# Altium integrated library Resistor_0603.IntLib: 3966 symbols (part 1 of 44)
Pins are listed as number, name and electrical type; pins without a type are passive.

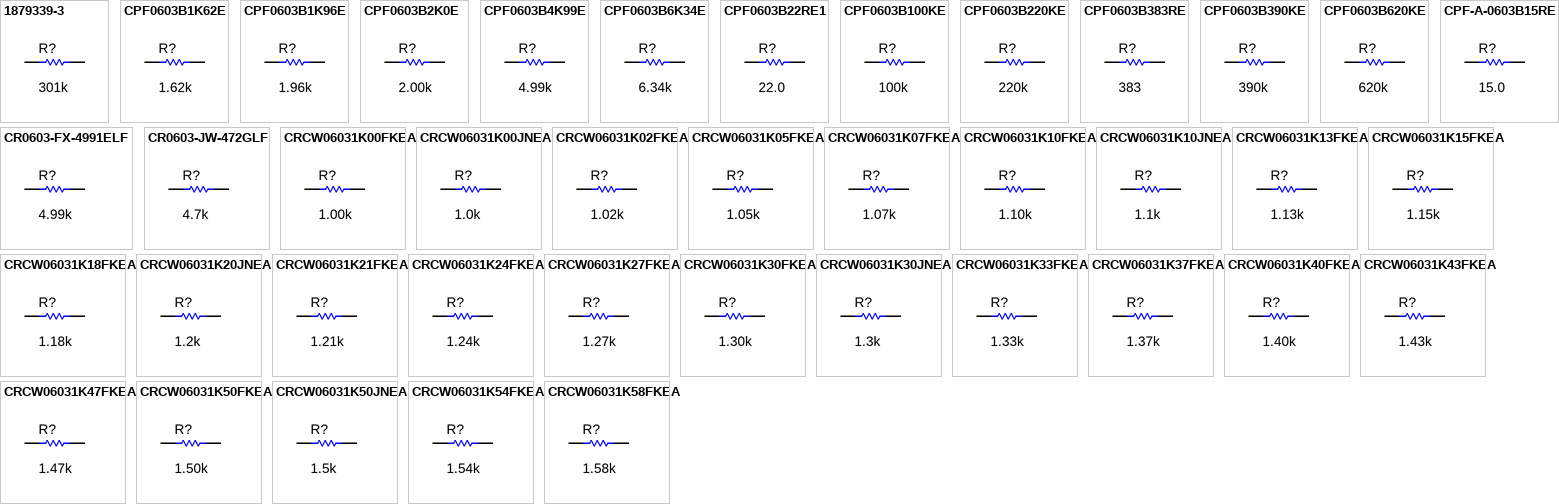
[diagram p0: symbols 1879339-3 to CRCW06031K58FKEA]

## 1879339-3
designator R?  ValueDisplayed: 301k  (hidden comment: 1879339-3)
RES, 301 k, 1%, 0.063 W, 0603; Manufacturer: TE Connectivity; CompType: Resistor; Value: 301k; Res_ohm: 301000; Tolerance_%: 1; Power_W: 0.063; Value2: 0.063W; VDC_V: 50; TempCo: 50 ppm/C; SizeArea_mm2: 1.28; SizeX_mm: 1.6; SizeY_mm: 0.8; EIA_Code: E96; U/M: EA; AEC Category: Q200; Green_Lifecycle: Active; Green_REACh: Passed
signal-integrity model Resistor
simulation model Resistor
footprint 0603
footprint 0603M
footprint 0603L
footprint 0603_HV
footprint 0603S
pins: 1, 2

## CPF0603B1K62E
designator R?  ValueDisplayed: 1.62k  (hidden comment: CPF0603B1K62E)
RES, 1.62 k, 0.1%, 0.063 W, 0603; Manufacturer: TE Connectivity; CompType: Resistor; Value: 1.62k; Res_ohm: 1620; Value_Code: 1k62; Tolerance_%: 0.1; Power_W: 0.063; Value2: 0.063W; VDC_V: 50; TempCo: 25 ppm/C; SizeArea_mm2: 1.28; SizeX_mm: 1.6; SizeY_mm: 0.8; SizeZ_mm: 1; EIA_Code: E192; U/M: EA; AEC Category: Q200
signal-integrity model Resistor
simulation model Resistor
footprint 0603
footprint 0603M
footprint 0603L
footprint 0603_HV
footprint 0603S
pins: 1, 2

## CPF0603B1K96E
designator R?  ValueDisplayed: 1.96k  (hidden comment: CPF0603B1K96E)
RES, 1.96 k, 0.1%, 0.063 W, 0603; Manufacturer: TE Connectivity; CompType: Resistor; Value: 1.96k; Res_ohm: 1960; Value_Code: 1k96; Tolerance_%: 0.1; Power_W: 0.063; Value2: 0.063W; VDC_V: 50; TempCo: 25 ppm/C; SizeArea_mm2: 1.28; SizeX_mm: 1.6; SizeY_mm: 0.8; SizeZ_mm: 1; EIA_Code: E192; U/M: EA; AEC Category: Q200
signal-integrity model Resistor
simulation model Resistor
footprint 0603
footprint 0603M
footprint 0603L
footprint 0603_HV
footprint 0603S
pins: 1, 2

## CPF0603B2K0E
designator R?  ValueDisplayed: 2.00k  (hidden comment: CPF0603B2K0E)
RES, 2.00 k, 0.1%, 0.063 W, 0603; Manufacturer: TE Connectivity; CompType: Resistor; Value: 2.00k; Res_ohm: 2000; Value_Code: 2k00; Tolerance_%: 0.1; Power_W: 0.063; Value2: 0.063W; VDC_V: 50; TempCo: 25 ppm/C; SizeArea_mm2: 1.24; SizeX_mm: 1.55; SizeY_mm: 0.8; SizeZ_mm: 0.55; EIA_Code: E192; U/M: EA; AEC Category: Q200; AEC Qualified: N; Green_Lifecycle: Active; Green_REACh: Passed
signal-integrity model Resistor
simulation model Resistor
footprint CPF0603
pins: 1, 2

## CPF0603B4K99E
designator R?  ValueDisplayed: 4.99k  (hidden comment: CPF0603B4K99E)
RES, 4.99 k, 0.1%, 0.063 W, 0603; Manufacturer: TE Connectivity; CompType: Resistor; Value: 4.99k; Res_ohm: 4990; Value_Code: 4k99; Tolerance_%: 0.1; Power_W: 0.063; Value2: 0.063W; VDC_V: 50; TempCo: 25 ppm/C; SizeArea_mm2: 1.28; SizeX_mm: 1.6; SizeY_mm: 0.8; SizeZ_mm: 1; EIA_Code: E192; U/M: EA; AEC Category: Q200; Green_Lifecycle: Active; Green_REACh: Passed
signal-integrity model Resistor
simulation model Resistor
footprint 0603
footprint 0603M
footprint 0603L
footprint 0603_HV
footprint 0603S
pins: 1, 2

## CPF0603B6K34E
designator R?  ValueDisplayed: 6.34k  (hidden comment: CPF0603B6K34E)
RES, 6.34 k, 0.1%, 0.063 W, 0603; Manufacturer: TE Connectivity; CompType: Resistor; Value: 6.34k; Res_ohm: 6340; Value_Code: 6k34; Tolerance_%: 0.1; Power_W: 0.063; Value2: 0.063W; VDC_V: 50; TempCo: 25 ppm/C; SizeArea_mm2: 1.28; SizeX_mm: 1.6; SizeY_mm: 0.8; SizeZ_mm: 1; EIA_Code: E192; U/M: EA; AEC Category: Q200
signal-integrity model Resistor
simulation model Resistor
footprint 0603
footprint 0603M
footprint 0603L
footprint 0603_HV
footprint 0603S
pins: 1, 2

## CPF0603B22RE1
designator R?  ValueDisplayed: 22.0  (hidden comment: CPF0603B22RE1)
RES, 22.0, 0.1%, 0.063 W, 0603; Manufacturer: TE Connectivity; CompType: Resistor; Value: 22; Value_Code: 22R0; Tolerance_%: 0.1; Power_W: 0.063; Value2: 0.063W; TempCo: 25 ppm/C; SizeArea_mm2: 1.24; SizeX_mm: 1.55; SizeY_mm: 0.8; SizeZ_mm: 0.55; U/M: EA; AEC Category: Q200; AEC Qualified: N
signal-integrity model Resistor
simulation model Resistor
footprint CPF0603
pins: 1, 2

## CPF0603B100KE
designator R?  ValueDisplayed: 100k  (hidden comment: CPF0603B100KE)
RES, 100 k, 0.1%, 0.063 W, 0603; Manufacturer: TE Connectivity; CompType: Resistor; Value: 100k; Res_ohm: 100000; Tolerance_%: 0.1; Power_W: 0.063; Value2: 0.063W; VDC_V: 50; TempCo: 25 ppm/C; SizeArea_mm2: 1.28; SizeX_mm: 1.6; SizeY_mm: 0.8; SizeZ_mm: 1; EIA_Code: E192; U/M: EA; AEC Category: Q200; Green_Lifecycle: Active; Green_REACh: Passed
signal-integrity model Resistor
simulation model Resistor
footprint 0603
footprint 0603M
footprint 0603L
footprint 0603_HV
footprint 0603S
pins: 1, 2

## CPF0603B220KE
designator R?  ValueDisplayed: 220k  (hidden comment: CPF0603B220KE)
RES, 220 k, 0.1%, 0.063 W, 0603; Manufacturer: TE Connectivity; CompType: Resistor; Value: 220k; Res_ohm: 220000; Tolerance_%: 0.1; Power_W: 0.063; Value2: 0.063W; VDC_V: 50; TempCo: 25 ppm/C; SizeArea_mm2: 1.28; SizeX_mm: 1.6; SizeY_mm: 0.8; SizeZ_mm: 1; U/M: EA; AEC Category: Q200; AEC Qualified: N
signal-integrity model Resistor
simulation model Resistor
footprint 0603
footprint 0603M
footprint 0603L
footprint 0603_HV
footprint 0603S
pins: 1, 2

## CPF0603B383RE
designator R?  ValueDisplayed: 383  (hidden comment: CPF0603B383RE)
RES, 383, 0.1%, 0.063 W, 0603; Manufacturer: TE Connectivity; CompType: Resistor; Value: 383; Value_Code: 383R; Tolerance_%: 0.1; Power_W: 0.063; Value2: 0.063W; VDC_V: 50; TempCo: 25 ppm/C; SizeArea_mm2: 1.28; SizeX_mm: 1.6; SizeY_mm: 0.8; SizeZ_mm: 1; EIA_Code: E192; U/M: EA; AEC Category: Q200; Green_Lifecycle: Active; Green_REACh: Passed
signal-integrity model Resistor
simulation model Resistor
footprint 0603
footprint 0603M
footprint 0603L
footprint 0603_HV
footprint 0603S
pins: 1, 2

## CPF0603B390KE
designator R?  ValueDisplayed: 390k  (hidden comment: CPF0603B390KE)
RES, 390 k, 0.1%, 0.1 W, 0603; Manufacturer: TE Connectivity; CompType: Resistor; Value: 390k; Res_ohm: 390000; Tolerance_%: 0.1; Value2: 0.1W; VDC_V: 50; TempCo: 25 ppm/C; SizeArea_mm2: 1.28; SizeX_mm: 1.6; SizeY_mm: 0.8; SizeZ_mm: 1; U/M: EA; AEC Category: Q200; AEC Qualified: N; Green_Lifecycle: Active; Green_REACh: Passed
signal-integrity model Resistor
simulation model Resistor
footprint 0603
footprint 0603M
footprint 0603L
footprint 0603_HV
footprint 0603S
pins: 1, 2

## CPF0603B620KE
designator R?  ValueDisplayed: 620k  (hidden comment: CPF0603B620KE)
RES, 620 k, 0.1%, 0.063 W, 0603; Manufacturer: TE Connectivity; CompType: Resistor; Value: 620k; Res_ohm: 620000; Tolerance_%: 0.1; Power_W: 0.063; Value2: 0.063W; VDC_V: 50; TempCo: 25 ppm/C; SizeArea_mm2: 1.24; SizeX_mm: 1.55; SizeY_mm: 0.8; SizeZ_mm: 0.55; U/M: EA; AEC Category: Q200; AEC Qualified: N
signal-integrity model Resistor
simulation model Resistor
footprint CPF0603
pins: 1, 2

## CPF-A-0603B15RE
designator R?  ValueDisplayed: 15.0  (hidden comment: CPF-A-0603B15RE)
RES, 15.0, 0.1%, 0.063 W, AEC-Q200 Grade 0, 0603; Manufacturer: TE Connectivity; CompType: Resistor; Value: 15.0; Res_ohm: 15; Value_Code: 15R0; Tolerance_%: 0.1; Power_W: 0.063; Value2: 0.063W; TempCo: 25 ppm/C; SizeArea_mm2: 1.24; SizeX_mm: 1.55; SizeY_mm: 0.8; SizeZ_mm: 0.55; EIA_Code: E192; U/M: EA; AEC Category: Q200; AEC Qualified: Y; AEC Grade: 0
signal-integrity model Resistor
simulation model Resistor
footprint CPF0603
pins: 1, 2

## CR0603-FX-4991ELF
designator R?  ValueDisplayed: 4.99k  (hidden comment: CR0603-FX-4991ELF)
RES, 4.99 k, 1%, 0.1 W, 0603; Manufacturer: Bourns; CompType: Resistor; Value: 4.99k; Res_ohm: 4990; Value_Code: 4k99; Tolerance_%: 1; Power_W: 0.1; Value2: 0.1W; TempCo: 100 ppm/C; SizeArea_mm2: 1.28; SizeX_mm: 1.6; SizeY_mm: 0.8; EIA_Code: E96; U/M: EA; AEC Category: Q200; Green_Lifecycle: Active; Green_REACh: Passed
signal-integrity model Resistor
simulation model Resistor
footprint 0603
footprint 0603M
footprint 0603L
footprint 0603_HV
footprint 0603S
pins: 1, 2

## CR0603-JW-472GLF
designator R?  ValueDisplayed: 4.7k  (hidden comment: CR0603-JW-472GLF)
RES, 4.7 k, 5%, 0.1 W, 0603; Manufacturer: Bourns; CompType: Resistor; Value: 4.7k; Res_ohm: 4700; Value_Code: 4k70; Tolerance_%: 5; Power_W: 0.1; Value2: 0.1W; VDC_V: 50; TempCo: 200 ppm/C; SizeArea_mm2: 1.28; SizeX_mm: 1.6; SizeY_mm: 0.8; SizeZ_mm: 1; EIA_Code: E24; U/M: EA; AEC Category: Q200; AEC Qualified: N; Green_Lifecycle: Active; Green_REACh: Passed
signal-integrity model Resistor
simulation model Resistor
footprint 0603
footprint 0603M
footprint 0603L
footprint 0603_HV
footprint 0603S
pins: 1, 2

## CRCW06031K00FKEA
designator R?  ValueDisplayed: 1.00k  (hidden comment: CRCW06031K00FKEA)
RES, 1.00 k, 1%, 0.1 W, 0603; Manufacturer: Vishay-Dale; CompType: Resistor; Value: 1.00k; Res_ohm: 1000; Value_Code: 1k00; Tolerance_%: 1; Power_W: 0.1; Value2: 0.1W; VDC_V: 75; TempCo: 100 ppm/C; SizeArea_mm2: 1.28; SizeX_mm: 1.6; SizeY_mm: 0.8; EIA_Code: E96; U/M: EA; AEC Category: Q200; Green_Lifecycle: Active; Green_REACh: Passed
signal-integrity model Resistor
simulation model Resistor
footprint 0603
footprint 0603M
footprint 0603L
footprint 0603_HV
footprint 0603S
pins: 1, 2

## CRCW06031K00JNEA
designator R?  ValueDisplayed: 1.0k  (hidden comment: CRCW06031K00JNEA)
RES, 1.0 k, 5%, 0.1 W, 0603; Manufacturer: Vishay-Dale; CompType: Resistor; Value: 1.0k; Res_ohm: 1000; Value_Code: 1k00; Tolerance_%: 5; Power_W: 0.1; Value2: 0.1W; VDC_V: 75; TempCo: 200 ppm/C; SizeArea_mm2: 1.28; SizeX_mm: 1.6; SizeY_mm: 0.8; SizeZ_mm: 1; EIA_Code: E24; U/M: EA; AEC Category: Q200; Green_Lifecycle: Active; Green_REACh: Passed
signal-integrity model Resistor
simulation model Resistor
footprint 0603
footprint 0603M
footprint 0603L
footprint 0603_HV
footprint 0603S
pins: 1, 2

## CRCW06031K02FKEA
designator R?  ValueDisplayed: 1.02k  (hidden comment: CRCW06031K02FKEA)
RES, 1.02 k, 1%, 0.1 W, 0603; Manufacturer: Vishay-Dale; CompType: Resistor; Value: 1.02k; Res_ohm: 1020; Value_Code: 1k02; Tolerance_%: 1; Power_W: 0.1; Value2: 0.1W; VDC_V: 75; TempCo: 100 ppm/C; SizeArea_mm2: 1.28; SizeX_mm: 1.6; SizeY_mm: 0.8; EIA_Code: E96; U/M: EA; AEC Category: Q200; Green_Lifecycle: Active; Green_REACh: Passed
signal-integrity model Resistor
simulation model Resistor
footprint 0603
footprint 0603M
footprint 0603L
footprint 0603_HV
footprint 0603S
pins: 1, 2

## CRCW06031K05FKEA
designator R?  ValueDisplayed: 1.05k  (hidden comment: CRCW06031K05FKEA)
RES, 1.05 k, 1%, 0.1 W, 0603; Manufacturer: Vishay-Dale; CompType: Resistor; Value: 1.05k; Res_ohm: 1050; Value_Code: 1k05; Tolerance_%: 1; Power_W: 0.1; Value2: 0.1W; VDC_V: 75; TempCo: 100 ppm/C; SizeArea_mm2: 1.28; SizeX_mm: 1.6; SizeY_mm: 0.8; EIA_Code: E96; U/M: EA; AEC Category: Q200; Green_Lifecycle: Active; Green_REACh: Passed
signal-integrity model Resistor
simulation model Resistor
footprint 0603
footprint 0603M
footprint 0603L
footprint 0603_HV
footprint 0603S
pins: 1, 2

## CRCW06031K07FKEA
designator R?  ValueDisplayed: 1.07k  (hidden comment: CRCW06031K07FKEA)
RES, 1.07 k, 1%, 0.1 W, 0603; Manufacturer: Vishay-Dale; CompType: Resistor; Value: 1.07k; Res_ohm: 1070; Value_Code: 1k07; Tolerance_%: 1; Power_W: 0.1; Value2: 0.1W; VDC_V: 75; TempCo: 100 ppm/C; SizeArea_mm2: 1.28; SizeX_mm: 1.6; SizeY_mm: 0.8; EIA_Code: E96; U/M: EA; AEC Category: Q200; Green_Lifecycle: Active; Green_REACh: Passed
signal-integrity model Resistor
simulation model Resistor
footprint 0603
footprint 0603M
footprint 0603L
footprint 0603_HV
footprint 0603S
pins: 1, 2

## CRCW06031K10FKEA
designator R?  ValueDisplayed: 1.10k  (hidden comment: CRCW06031K10FKEA)
RES, 1.10 k, 1%, 0.1 W, 0603; Manufacturer: Vishay-Dale; CompType: Resistor; Value: 1.10k; Res_ohm: 1100; Value_Code: 1k10; Tolerance_%: 1; Power_W: 0.1; Value2: 0.1W; VDC_V: 75; TempCo: 100 ppm/C; SizeArea_mm2: 1.28; SizeX_mm: 1.6; SizeY_mm: 0.8; EIA_Code: E96; U/M: EA; AEC Category: Q200; Green_Lifecycle: Active; Green_REACh: Passed
signal-integrity model Resistor
simulation model Resistor
footprint 0603
footprint 0603M
footprint 0603L
footprint 0603_HV
footprint 0603S
pins: 1, 2

## CRCW06031K10JNEA
designator R?  ValueDisplayed: 1.1k  (hidden comment: CRCW06031K10JNEA)
RES, 1.1 k, 5%, 0.1 W, 0603; Manufacturer: Vishay-Dale; CompType: Resistor; Value: 1.1k; Res_ohm: 1100; Value_Code: 1k10; Tolerance_%: 5; Power_W: 0.1; Value2: 0.1W; VDC_V: 75; TempCo: 200 ppm/C; SizeArea_mm2: 1.28; SizeX_mm: 1.6; SizeY_mm: 0.8; SizeZ_mm: 1; EIA_Code: E24; U/M: EA; AEC Category: Q200; Green_Lifecycle: Active; Green_REACh: Passed
signal-integrity model Resistor
simulation model Resistor
footprint 0603
footprint 0603M
footprint 0603L
footprint 0603_HV
footprint 0603S
pins: 1, 2

## CRCW06031K13FKEA
designator R?  ValueDisplayed: 1.13k  (hidden comment: CRCW06031K13FKEA)
RES, 1.13 k, 1%, 0.1 W, 0603; Manufacturer: Vishay-Dale; CompType: Resistor; Value: 1.13k; Res_ohm: 1130; Value_Code: 1k13; Tolerance_%: 1; Power_W: 0.1; Value2: 0.1W; VDC_V: 75; TempCo: 100 ppm/C; SizeArea_mm2: 1.28; SizeX_mm: 1.6; SizeY_mm: 0.8; EIA_Code: E96; U/M: EA; AEC Category: Q200; Green_Lifecycle: Active; Green_REACh: Passed
signal-integrity model Resistor
simulation model Resistor
footprint 0603
footprint 0603M
footprint 0603L
footprint 0603_HV
footprint 0603S
pins: 1, 2

## CRCW06031K15FKEA
designator R?  ValueDisplayed: 1.15k  (hidden comment: CRCW06031K15FKEA)
RES, 1.15 k, 1%, 0.1 W, 0603; Manufacturer: Vishay-Dale; CompType: Resistor; Value: 1.15k; Res_ohm: 1150; Value_Code: 1k15; Tolerance_%: 1; Power_W: 0.1; Value2: 0.1W; VDC_V: 75; TempCo: 100 ppm/C; SizeArea_mm2: 1.28; SizeX_mm: 1.6; SizeY_mm: 0.8; EIA_Code: E96; U/M: EA; AEC Category: Q200
signal-integrity model Resistor
simulation model Resistor
footprint 0603
footprint 0603M
footprint 0603L
footprint 0603_HV
footprint 0603S
pins: 1, 2

## CRCW06031K18FKEA
designator R?  ValueDisplayed: 1.18k  (hidden comment: CRCW06031K18FKEA)
RES, 1.18 k, 1%, 0.1 W, 0603; Manufacturer: Vishay-Dale; CompType: Resistor; Value: 1.18k; Res_ohm: 1180; Value_Code: 1k18; Tolerance_%: 1; Power_W: 0.1; Value2: 0.1W; VDC_V: 75; TempCo: 100 ppm/C; SizeArea_mm2: 1.28; SizeX_mm: 1.6; SizeY_mm: 0.8; EIA_Code: E96; U/M: EA; AEC Category: Q200
signal-integrity model Resistor
simulation model Resistor
footprint 0603
footprint 0603M
footprint 0603L
footprint 0603_HV
footprint 0603S
pins: 1, 2

## CRCW06031K20JNEA
designator R?  ValueDisplayed: 1.2k  (hidden comment: CRCW06031K20JNEA)
RES, 1.2 k, 5%, 0.1 W, 0603; Manufacturer: Vishay-Dale; CompType: Resistor; Value: 1.2k; Res_ohm: 1200; Value_Code: 1k20; Tolerance_%: 5; Power_W: 0.1; Value2: 0.1W; VDC_V: 75; TempCo: 200 ppm/C; SizeArea_mm2: 1.28; SizeX_mm: 1.6; SizeY_mm: 0.8; SizeZ_mm: 1; EIA_Code: E24; U/M: EA; AEC Category: Q200; Green_Lifecycle: Active; Green_REACh: Passed
signal-integrity model Resistor
simulation model Resistor
footprint 0603
footprint 0603M
footprint 0603L
footprint 0603_HV
footprint 0603S
pins: 1, 2

## CRCW06031K21FKEA
designator R?  ValueDisplayed: 1.21k  (hidden comment: CRCW06031K21FKEA)
RES, 1.21 k, 1%, 0.1 W, 0603; Manufacturer: Vishay-Dale; CompType: Resistor; Value: 1.21k; Res_ohm: 1210; Value_Code: 1k21; Tolerance_%: 1; Power_W: 0.1; Value2: 0.1W; VDC_V: 75; TempCo: 100 ppm/C; SizeArea_mm2: 1.28; SizeX_mm: 1.6; SizeY_mm: 0.8; EIA_Code: E96; U/M: EA; AEC Category: Q200; Green_Lifecycle: Active; Green_REACh: Passed
signal-integrity model Resistor
simulation model Resistor
footprint 0603
footprint 0603M
footprint 0603L
footprint 0603_HV
footprint 0603S
pins: 1, 2

## CRCW06031K24FKEA
designator R?  ValueDisplayed: 1.24k  (hidden comment: CRCW06031K24FKEA)
RES, 1.24 k, 1%, 0.1 W, 0603; Manufacturer: Vishay-Dale; CompType: Resistor; Value: 1.24k; Res_ohm: 1240; Value_Code: 1k24; Tolerance_%: 1; Power_W: 0.1; Value2: 0.1W; VDC_V: 75; TempCo: 100 ppm/C; SizeArea_mm2: 1.28; SizeX_mm: 1.6; SizeY_mm: 0.8; EIA_Code: E96; U/M: EA; AEC Category: Q200; Green_Lifecycle: Active; Green_REACh: Passed
signal-integrity model Resistor
simulation model Resistor
footprint 0603
footprint 0603M
footprint 0603L
footprint 0603_HV
footprint 0603S
pins: 1, 2

## CRCW06031K27FKEA
designator R?  ValueDisplayed: 1.27k  (hidden comment: CRCW06031K27FKEA)
RES, 1.27 k, 1%, 0.1 W, 0603; Manufacturer: Vishay-Dale; CompType: Resistor; Value: 1.27k; Res_ohm: 1270; Value_Code: 1k27; Tolerance_%: 1; Power_W: 0.1; Value2: 0.1W; VDC_V: 75; TempCo: 100 ppm/C; SizeArea_mm2: 1.28; SizeX_mm: 1.6; SizeY_mm: 0.8; EIA_Code: E96; U/M: EA; AEC Category: Q200; Green_Lifecycle: Active; Green_REACh: Passed
signal-integrity model Resistor
simulation model Resistor
footprint 0603
footprint 0603M
footprint 0603L
footprint 0603_HV
footprint 0603S
pins: 1, 2

## CRCW06031K30FKEA
designator R?  ValueDisplayed: 1.30k  (hidden comment: CRCW06031K30FKEA)
RES, 1.30 k, 1%, 0.1 W, 0603; Manufacturer: Vishay-Dale; CompType: Resistor; Value: 1.30k; Res_ohm: 1300; Value_Code: 1k30; Tolerance_%: 1; Power_W: 0.1; Value2: 0.1W; VDC_V: 75; TempCo: 100 ppm/C; SizeArea_mm2: 1.28; SizeX_mm: 1.6; SizeY_mm: 0.8; EIA_Code: E96; U/M: EA; AEC Category: Q200
signal-integrity model Resistor
simulation model Resistor
footprint 0603
footprint 0603M
footprint 0603L
footprint 0603_HV
footprint 0603S
pins: 1, 2

## CRCW06031K30JNEA
designator R?  ValueDisplayed: 1.3k  (hidden comment: CRCW06031K30JNEA)
RES, 1.3 k, 5%, 0.1 W, 0603; Manufacturer: Vishay-Dale; CompType: Resistor; Value: 1.3k; Res_ohm: 1300; Value_Code: 1k30; Tolerance_%: 5; Power_W: 0.1; Value2: 0.1W; VDC_V: 75; TempCo: 200 ppm/C; SizeArea_mm2: 1.28; SizeX_mm: 1.6; SizeY_mm: 0.8; SizeZ_mm: 1; EIA_Code: E24; U/M: EA; AEC Category: Q200
signal-integrity model Resistor
simulation model Resistor
footprint 0603
footprint 0603M
footprint 0603L
footprint 0603_HV
footprint 0603S
pins: 1, 2

## CRCW06031K33FKEA
designator R?  ValueDisplayed: 1.33k  (hidden comment: CRCW06031K33FKEA)
RES, 1.33 k, 1%, 0.1 W, 0603; Manufacturer: Vishay-Dale; CompType: Resistor; Value: 1.33k; Res_ohm: 1330; Value_Code: 1k33; Tolerance_%: 1; Power_W: 0.1; Value2: 0.1W; VDC_V: 75; TempCo: 100 ppm/C; SizeArea_mm2: 1.28; SizeX_mm: 1.6; SizeY_mm: 0.8; EIA_Code: E96; U/M: EA; AEC Category: Q200
signal-integrity model Resistor
simulation model Resistor
footprint 0603
footprint 0603M
footprint 0603L
footprint 0603_HV
footprint 0603S
pins: 1, 2

## CRCW06031K37FKEA
designator R?  ValueDisplayed: 1.37k  (hidden comment: CRCW06031K37FKEA)
RES, 1.37 k, 1%, 0.1 W, 0603; Manufacturer: Vishay-Dale; CompType: Resistor; Value: 1.37k; Res_ohm: 1370; Value_Code: 1k37; Tolerance_%: 1; Power_W: 0.1; Value2: 0.1W; VDC_V: 75; TempCo: 100 ppm/C; SizeArea_mm2: 1.28; SizeX_mm: 1.6; SizeY_mm: 0.8; EIA_Code: E96; U/M: EA; AEC Category: Q200; Green_Lifecycle: Active; Green_REACh: Passed
signal-integrity model Resistor
simulation model Resistor
footprint 0603
footprint 0603M
footprint 0603L
footprint 0603_HV
footprint 0603S
pins: 1, 2

## CRCW06031K40FKEA
designator R?  ValueDisplayed: 1.40k  (hidden comment: CRCW06031K40FKEA)
RES, 1.40 k, 1%, 0.1 W, 0603; Manufacturer: Vishay-Dale; CompType: Resistor; Value: 1.40k; Res_ohm: 1400; Value_Code: 1k40; Tolerance_%: 1; Power_W: 0.1; Value2: 0.1W; VDC_V: 75; TempCo: 100 ppm/C; SizeArea_mm2: 1.28; SizeX_mm: 1.6; SizeY_mm: 0.8; EIA_Code: E96; U/M: EA; AEC Category: Q200; Green_Lifecycle: Active; Green_REACh: Passed
signal-integrity model Resistor
simulation model Resistor
footprint 0603
footprint 0603M
footprint 0603L
footprint 0603_HV
footprint 0603S
pins: 1, 2

## CRCW06031K43FKEA
designator R?  ValueDisplayed: 1.43k  (hidden comment: CRCW06031K43FKEA)
RES, 1.43 k, 1%, 0.1 W, 0603; Manufacturer: Vishay-Dale; CompType: Resistor; Value: 1.43k; Res_ohm: 1430; Value_Code: 1k43; Tolerance_%: 1; Power_W: 0.1; Value2: 0.1W; VDC_V: 75; TempCo: 100 ppm/C; SizeArea_mm2: 1.28; SizeX_mm: 1.6; SizeY_mm: 0.8; EIA_Code: E96; U/M: EA; AEC Category: Q200; Green_Lifecycle: Active; Green_REACh: Passed
signal-integrity model Resistor
simulation model Resistor
footprint 0603
footprint 0603M
footprint 0603L
footprint 0603_HV
footprint 0603S
pins: 1, 2

## CRCW06031K47FKEA
designator R?  ValueDisplayed: 1.47k  (hidden comment: CRCW06031K47FKEA)
RES, 1.47 k, 1%, 0.1 W, 0603; Manufacturer: Vishay-Dale; CompType: Resistor; Value: 1.47k; Res_ohm: 1470; Value_Code: 1k47; Tolerance_%: 1; Power_W: 0.1; Value2: 0.1W; VDC_V: 75; TempCo: 100 ppm/C; SizeArea_mm2: 1.28; SizeX_mm: 1.6; SizeY_mm: 0.8; EIA_Code: E96; U/M: EA; AEC Category: Q200
signal-integrity model Resistor
simulation model Resistor
footprint 0603
footprint 0603M
footprint 0603L
footprint 0603_HV
footprint 0603S
pins: 1, 2

## CRCW06031K50FKEA
designator R?  ValueDisplayed: 1.50k  (hidden comment: CRCW06031K50FKEA)
RES, 1.50 k, 1%, 0.1 W, 0603; Manufacturer: Vishay-Dale; CompType: Resistor; Value: 1.50k; Res_ohm: 1500; Value_Code: 1k50; Tolerance_%: 1; Power_W: 0.1; Value2: 0.1W; VDC_V: 75; TempCo: 100 ppm/C; SizeArea_mm2: 1.28; SizeX_mm: 1.6; SizeY_mm: 0.8; EIA_Code: E96; U/M: EA; AEC Category: Q200; Green_Lifecycle: Active; Green_REACh: Passed
signal-integrity model Resistor
simulation model Resistor
footprint 0603
footprint 0603M
footprint 0603L
footprint 0603_HV
footprint 0603S
pins: 1, 2

## CRCW06031K50JNEA
designator R?  ValueDisplayed: 1.5k  (hidden comment: CRCW06031K50JNEA)
RES, 1.5 k, 5%, 0.1 W, 0603; Manufacturer: Vishay-Dale; CompType: Resistor; Value: 1.5k; Res_ohm: 1500; Value_Code: 1k50; Tolerance_%: 5; Power_W: 0.1; Value2: 0.1W; VDC_V: 75; TempCo: 200 ppm/C; SizeArea_mm2: 1.28; SizeX_mm: 1.6; SizeY_mm: 0.8; SizeZ_mm: 1; EIA_Code: E24; U/M: EA; AEC Category: Q200; Green_Lifecycle: Active; Green_REACh: Passed
signal-integrity model Resistor
simulation model Resistor
footprint 0603
footprint 0603M
footprint 0603L
footprint 0603_HV
footprint 0603S
pins: 1, 2

## CRCW06031K54FKEA
designator R?  ValueDisplayed: 1.54k  (hidden comment: CRCW06031K54FKEA)
RES, 1.54 k, 1%, 0.1 W, 0603; Manufacturer: Vishay-Dale; CompType: Resistor; Value: 1.54k; Res_ohm: 1540; Value_Code: 1k54; Tolerance_%: 1; Power_W: 0.1; Value2: 0.1W; VDC_V: 75; TempCo: 100 ppm/C; SizeArea_mm2: 1.28; SizeX_mm: 1.6; SizeY_mm: 0.8; EIA_Code: E96; U/M: EA; AEC Category: Q200; Green_Lifecycle: Active; Green_REACh: Passed
signal-integrity model Resistor
simulation model Resistor
footprint 0603
footprint 0603M
footprint 0603L
footprint 0603_HV
footprint 0603S
pins: 1, 2

## CRCW06031K58FKEA
designator R?  ValueDisplayed: 1.58k  (hidden comment: CRCW06031K58FKEA)
RES, 1.58 k, 1%, 0.1 W, 0603; Manufacturer: Vishay-Dale; CompType: Resistor; Value: 1.58k; Res_ohm: 1580; Value_Code: 1k58; Tolerance_%: 1; Power_W: 0.1; Value2: 0.1W; VDC_V: 75; TempCo: 100 ppm/C; SizeArea_mm2: 1.28; SizeX_mm: 1.6; SizeY_mm: 0.8; EIA_Code: E96; U/M: EA; AEC Category: Q200; Green_Lifecycle: Active; Green_REACh: Passed
signal-integrity model Resistor
simulation model Resistor
footprint 0603
footprint 0603M
footprint 0603L
footprint 0603_HV
footprint 0603S
pins: 1, 2

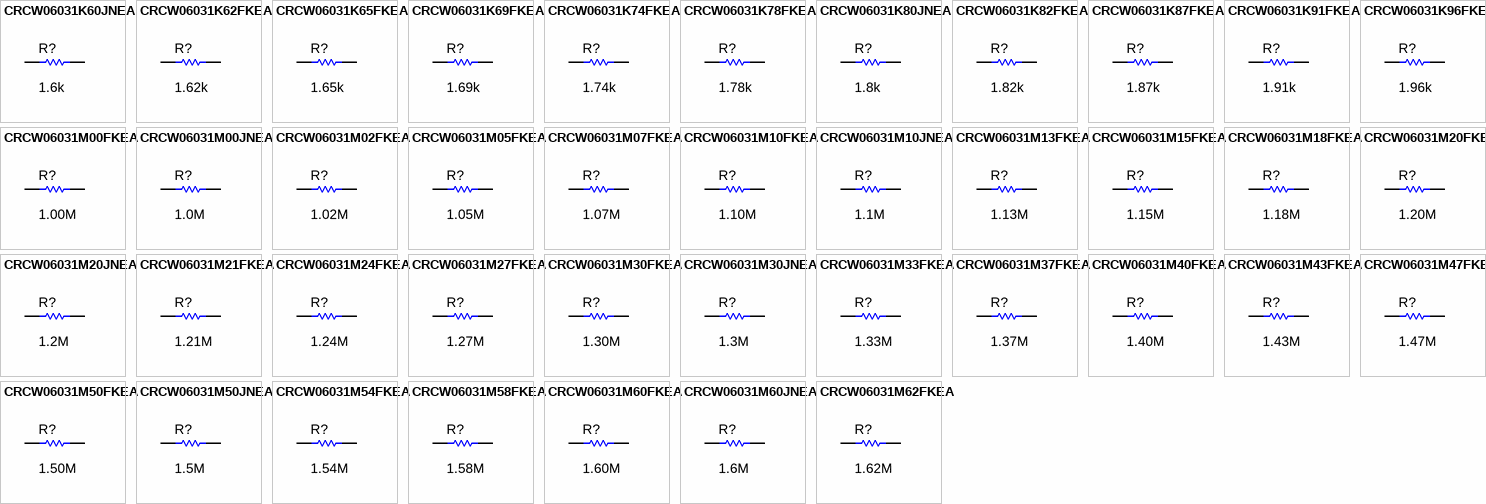
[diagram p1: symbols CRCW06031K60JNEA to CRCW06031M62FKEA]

## CRCW06031K60JNEA
designator R?  ValueDisplayed: 1.6k  (hidden comment: CRCW06031K60JNEA)
RES, 1.6 k, 5%, 0.1 W, 0603; Manufacturer: Vishay-Dale; CompType: Resistor; Value: 1.6k; Res_ohm: 1600; Value_Code: 1k60; Tolerance_%: 5; Power_W: 0.1; Value2: 0.1W; VDC_V: 75; TempCo: 200 ppm/C; SizeArea_mm2: 1.28; SizeX_mm: 1.6; SizeY_mm: 0.8; SizeZ_mm: 1; EIA_Code: E24; U/M: EA; AEC Category: Q200; Green_Lifecycle: Active; Green_REACh: Passed
signal-integrity model Resistor
simulation model Resistor
footprint 0603
footprint 0603M
footprint 0603L
footprint 0603_HV
footprint 0603S
pins: 1, 2

## CRCW06031K62FKEA
designator R?  ValueDisplayed: 1.62k  (hidden comment: CRCW06031K62FKEA)
RES, 1.62 k, 1%, 0.1 W, 0603; Manufacturer: Vishay-Dale; CompType: Resistor; Value: 1.62k; Res_ohm: 1620; Value_Code: 1k62; Tolerance_%: 1; Power_W: 0.1; Value2: 0.1W; VDC_V: 75; TempCo: 100 ppm/C; SizeArea_mm2: 1.28; SizeX_mm: 1.6; SizeY_mm: 0.8; EIA_Code: E96; U/M: EA; AEC Category: Q200; Green_Lifecycle: Active; Green_REACh: Passed
signal-integrity model Resistor
simulation model Resistor
footprint 0603
footprint 0603M
footprint 0603L
footprint 0603_HV
footprint 0603S
pins: 1, 2

## CRCW06031K65FKEA
designator R?  ValueDisplayed: 1.65k  (hidden comment: CRCW06031K65FKEA)
RES, 1.65 k, 1%, 0.1 W, 0603; Manufacturer: Vishay-Dale; CompType: Resistor; Value: 1.65k; Res_ohm: 1650; Value_Code: 1k65; Tolerance_%: 1; Power_W: 0.1; Value2: 0.1W; VDC_V: 75; TempCo: 100 ppm/C; SizeArea_mm2: 1.28; SizeX_mm: 1.6; SizeY_mm: 0.8; EIA_Code: E96; U/M: EA; AEC Category: Q200; Green_Lifecycle: Active; Green_REACh: Passed
signal-integrity model Resistor
simulation model Resistor
footprint 0603
footprint 0603M
footprint 0603L
footprint 0603_HV
footprint 0603S
pins: 1, 2

## CRCW06031K69FKEA
designator R?  ValueDisplayed: 1.69k  (hidden comment: CRCW06031K69FKEA)
RES, 1.69 k, 1%, 0.1 W, 0603; Manufacturer: Vishay-Dale; CompType: Resistor; Value: 1.69k; Res_ohm: 1690; Value_Code: 1k69; Tolerance_%: 1; Power_W: 0.1; Value2: 0.1W; VDC_V: 75; TempCo: 100 ppm/C; SizeArea_mm2: 1.28; SizeX_mm: 1.6; SizeY_mm: 0.8; EIA_Code: E96; U/M: EA; AEC Category: Q200
signal-integrity model Resistor
simulation model Resistor
footprint 0603
footprint 0603M
footprint 0603L
footprint 0603_HV
footprint 0603S
pins: 1, 2

## CRCW06031K74FKEA
designator R?  ValueDisplayed: 1.74k  (hidden comment: CRCW06031K74FKEA)
RES, 1.74 k, 1%, 0.1 W, 0603; Manufacturer: Vishay-Dale; CompType: Resistor; Value: 1.74k; Res_ohm: 1740; Value_Code: 1k74; Tolerance_%: 1; Power_W: 0.1; Value2: 0.1W; VDC_V: 75; TempCo: 100 ppm/C; SizeArea_mm2: 1.28; SizeX_mm: 1.6; SizeY_mm: 0.8; EIA_Code: E96; U/M: EA; AEC Category: Q200; Green_Lifecycle: Active; Green_REACh: Passed
signal-integrity model Resistor
simulation model Resistor
footprint 0603
footprint 0603M
footprint 0603L
footprint 0603_HV
footprint 0603S
pins: 1, 2

## CRCW06031K78FKEA
designator R?  ValueDisplayed: 1.78k  (hidden comment: CRCW06031K78FKEA)
RES, 1.78 k, 1%, 0.1 W, 0603; Manufacturer: Vishay-Dale; CompType: Resistor; Value: 1.78k; Res_ohm: 1780; Value_Code: 1k78; Tolerance_%: 1; Power_W: 0.1; Value2: 0.1W; VDC_V: 75; TempCo: 100 ppm/C; SizeArea_mm2: 1.28; SizeX_mm: 1.6; SizeY_mm: 0.8; EIA_Code: E96; U/M: EA; AEC Category: Q200; Green_Lifecycle: Active; Green_REACh: Passed
signal-integrity model Resistor
simulation model Resistor
footprint 0603
footprint 0603M
footprint 0603L
footprint 0603_HV
footprint 0603S
pins: 1, 2

## CRCW06031K80JNEA
designator R?  ValueDisplayed: 1.8k  (hidden comment: CRCW06031K80JNEA)
RES, 1.8 k, 5%, 0.1 W, 0603; Manufacturer: Vishay-Dale; CompType: Resistor; Value: 1.8k; Res_ohm: 1800; Value_Code: 1k80; Tolerance_%: 5; Power_W: 0.1; Value2: 0.1W; VDC_V: 75; TempCo: 200 ppm/C; SizeArea_mm2: 1.28; SizeX_mm: 1.6; SizeY_mm: 0.8; SizeZ_mm: 1; EIA_Code: E24; U/M: EA; AEC Category: Q200; Green_Lifecycle: Active; Green_REACh: Passed
signal-integrity model Resistor
simulation model Resistor
footprint 0603
footprint 0603M
footprint 0603L
footprint 0603_HV
footprint 0603S
pins: 1, 2

## CRCW06031K82FKEA
designator R?  ValueDisplayed: 1.82k  (hidden comment: CRCW06031K82FKEA)
RES, 1.82 k, 1%, 0.1 W, 0603; Manufacturer: Vishay-Dale; CompType: Resistor; Value: 1.82k; Res_ohm: 1820; Value_Code: 1k82; Tolerance_%: 1; Power_W: 0.1; Value2: 0.1W; VDC_V: 75; TempCo: 100 ppm/C; SizeArea_mm2: 1.28; SizeX_mm: 1.6; SizeY_mm: 0.8; EIA_Code: E96; U/M: EA; AEC Category: Q200
signal-integrity model Resistor
simulation model Resistor
footprint 0603
footprint 0603M
footprint 0603L
footprint 0603_HV
footprint 0603S
pins: 1, 2

## CRCW06031K87FKEA
designator R?  ValueDisplayed: 1.87k  (hidden comment: CRCW06031K87FKEA)
RES, 1.87 k, 1%, 0.1 W, 0603; Manufacturer: Vishay-Dale; CompType: Resistor; Value: 1.87k; Res_ohm: 1870; Value_Code: 1k87; Tolerance_%: 1; Power_W: 0.1; Value2: 0.1W; VDC_V: 75; TempCo: 100 ppm/C; SizeArea_mm2: 1.28; SizeX_mm: 1.6; SizeY_mm: 0.8; EIA_Code: E96; U/M: EA; AEC Category: Q200; Green_Lifecycle: Active; Green_REACh: Passed
signal-integrity model Resistor
simulation model Resistor
footprint 0603
footprint 0603M
footprint 0603L
footprint 0603_HV
footprint 0603S
pins: 1, 2

## CRCW06031K91FKEA
designator R?  ValueDisplayed: 1.91k  (hidden comment: CRCW06031K91FKEA)
RES, 1.91 k, 1%, 0.1 W, 0603; Manufacturer: Vishay-Dale; CompType: Resistor; Value: 1.91k; Res_ohm: 1910; Value_Code: 1k91; Tolerance_%: 1; Power_W: 0.1; Value2: 0.1W; VDC_V: 75; TempCo: 100 ppm/C; SizeArea_mm2: 1.28; SizeX_mm: 1.6; SizeY_mm: 0.8; EIA_Code: E96; U/M: EA; AEC Category: Q200
signal-integrity model Resistor
simulation model Resistor
footprint 0603
footprint 0603M
footprint 0603L
footprint 0603_HV
footprint 0603S
pins: 1, 2

## CRCW06031K96FKEA
designator R?  ValueDisplayed: 1.96k  (hidden comment: CRCW06031K96FKEA)
RES, 1.96 k, 1%, 0.1 W, 0603; Manufacturer: Vishay-Dale; CompType: Resistor; Value: 1.96k; Res_ohm: 1960; Value_Code: 1k96; Tolerance_%: 1; Power_W: 0.1; Value2: 0.1W; VDC_V: 75; TempCo: 100 ppm/C; SizeArea_mm2: 1.28; SizeX_mm: 1.6; SizeY_mm: 0.8; EIA_Code: E96; U/M: EA; AEC Category: Q200
signal-integrity model Resistor
simulation model Resistor
footprint 0603
footprint 0603M
footprint 0603L
footprint 0603_HV
footprint 0603S
pins: 1, 2

## CRCW06031M00FKEA
designator R?  ValueDisplayed: 1.00M  (hidden comment: CRCW06031M00FKEA)
RES, 1.00 M, 1%, 0.1 W, 0603; Manufacturer: Vishay-Dale; CompType: Resistor; Value: 1.00Meg; Res_ohm: 1000000; Value_Code: 1M00; Tolerance_%: 1; Power_W: 0.1; Value2: 0.1W; VDC_V: 75; TempCo: 100 ppm/C; SizeArea_mm2: 1.28; SizeX_mm: 1.6; SizeY_mm: 0.8; EIA_Code: E96; U/M: EA; AEC Category: Q200; Green_Lifecycle: Active; Green_REACh: Passed
signal-integrity model Resistor
simulation model Resistor
footprint 0603
footprint 0603M
footprint 0603L
footprint 0603_HV
footprint 0603S
pins: 1, 2

## CRCW06031M00JNEA
designator R?  ValueDisplayed: 1.0M  (hidden comment: CRCW06031M00JNEA)
RES, 1.0 M, 5%, 0.1 W, 0603; Manufacturer: Vishay-Dale; CompType: Resistor; Value: 1.0Meg; Res_ohm: 1000000; Value_Code: 1M00; Tolerance_%: 5; Power_W: 0.1; Value2: 0.1W; VDC_V: 75; TempCo: 200 ppm/C; SizeArea_mm2: 1.28; SizeX_mm: 1.6; SizeY_mm: 0.8; SizeZ_mm: 1; EIA_Code: E24; U/M: EA; AEC Category: Q200; Green_Lifecycle: Active; Green_REACh: Passed
signal-integrity model Resistor
simulation model Resistor
footprint 0603
footprint 0603M
footprint 0603L
footprint 0603_HV
footprint 0603S
pins: 1, 2

## CRCW06031M02FKEA
designator R?  ValueDisplayed: 1.02M  (hidden comment: CRCW06031M02FKEA)
RES, 1.02 M, 1%, 0.1 W, 0603; Manufacturer: Vishay-Dale; CompType: Resistor; Value: 1.02Meg; Res_ohm: 1020000; Value_Code: 1M02; Tolerance_%: 1; Power_W: 0.1; Value2: 0.1W; VDC_V: 75; TempCo: 100 ppm/C; SizeArea_mm2: 1.28; SizeX_mm: 1.6; SizeY_mm: 0.8; EIA_Code: E96; U/M: EA; AEC Category: Q200
signal-integrity model Resistor
simulation model Resistor
footprint 0603
footprint 0603M
footprint 0603L
footprint 0603_HV
footprint 0603S
pins: 1, 2

## CRCW06031M05FKEA
designator R?  ValueDisplayed: 1.05M  (hidden comment: CRCW06031M05FKEA)
RES, 1.05 M, 1%, 0.1 W, 0603; Manufacturer: Vishay-Dale; CompType: Resistor; Value: 1.05Meg; Res_ohm: 1050000; Value_Code: 1M05; Tolerance_%: 1; Power_W: 0.1; Value2: 0.1W; VDC_V: 75; TempCo: 100 ppm/C; SizeArea_mm2: 1.28; SizeX_mm: 1.6; SizeY_mm: 0.8; EIA_Code: E96; U/M: EA; AEC Category: Q200; Green_Lifecycle: Active; Green_REACh: Passed
signal-integrity model Resistor
simulation model Resistor
footprint 0603
footprint 0603M
footprint 0603L
footprint 0603_HV
footprint 0603S
pins: 1, 2

## CRCW06031M07FKEA
designator R?  ValueDisplayed: 1.07M  (hidden comment: CRCW06031M07FKEA)
RES, 1.07 M, 1%, 0.1 W, 0603; Manufacturer: Vishay-Dale; CompType: Resistor; Value: 1.07Meg; Res_ohm: 1070000; Value_Code: 1M07; Tolerance_%: 1; Power_W: 0.1; Value2: 0.1W; VDC_V: 75; TempCo: 100 ppm/C; SizeArea_mm2: 1.28; SizeX_mm: 1.6; SizeY_mm: 0.8; EIA_Code: E96; U/M: EA; AEC Category: Q200; Green_Lifecycle: Active; Green_REACh: Passed
signal-integrity model Resistor
simulation model Resistor
footprint 0603
footprint 0603M
footprint 0603L
footprint 0603_HV
footprint 0603S
pins: 1, 2

## CRCW06031M10FKEA
designator R?  ValueDisplayed: 1.10M  (hidden comment: CRCW06031M10FKEA)
RES, 1.10 M, 1%, 0.1 W, 0603; Manufacturer: Vishay-Dale; CompType: Resistor; Value: 1.10Meg; Res_ohm: 1100000; Value_Code: 1M10; Tolerance_%: 1; Power_W: 0.1; Value2: 0.1W; VDC_V: 75; TempCo: 100 ppm/C; SizeArea_mm2: 1.28; SizeX_mm: 1.6; SizeY_mm: 0.8; EIA_Code: E96; U/M: EA; AEC Category: Q200; Green_Lifecycle: Active; Green_REACh: Passed
signal-integrity model Resistor
simulation model Resistor
footprint 0603
footprint 0603M
footprint 0603L
footprint 0603_HV
footprint 0603S
pins: 1, 2

## CRCW06031M10JNEA
designator R?  ValueDisplayed: 1.1M  (hidden comment: CRCW06031M10JNEA)
RES, 1.1 M, 5%, 0.1 W, 0603; Manufacturer: Vishay-Dale; CompType: Resistor; Value: 1.1Meg; Res_ohm: 1100000; Value_Code: 1M10; Tolerance_%: 5; Power_W: 0.1; Value2: 0.1W; VDC_V: 75; TempCo: 200 ppm/C; SizeArea_mm2: 1.28; SizeX_mm: 1.6; SizeY_mm: 0.8; SizeZ_mm: 1; EIA_Code: E24; U/M: EA; AEC Category: Q200; Green_Lifecycle: Active; Green_REACh: Passed
signal-integrity model Resistor
simulation model Resistor
footprint 0603
footprint 0603M
footprint 0603L
footprint 0603_HV
footprint 0603S
pins: 1, 2

## CRCW06031M13FKEA
designator R?  ValueDisplayed: 1.13M  (hidden comment: CRCW06031M13FKEA)
RES, 1.13 M, 1%, 0.1 W, 0603; Manufacturer: Vishay-Dale; CompType: Resistor; Value: 1.13Meg; Res_ohm: 1130000; Value_Code: 1M13; Tolerance_%: 1; Power_W: 0.1; Value2: 0.1W; VDC_V: 75; TempCo: 100 ppm/C; SizeArea_mm2: 1.28; SizeX_mm: 1.6; SizeY_mm: 0.8; EIA_Code: E96; U/M: EA; AEC Category: Q200; Green_Lifecycle: Active; Green_REACh: Passed
signal-integrity model Resistor
simulation model Resistor
footprint 0603
footprint 0603M
footprint 0603L
footprint 0603_HV
footprint 0603S
pins: 1, 2

## CRCW06031M15FKEA
designator R?  ValueDisplayed: 1.15M  (hidden comment: CRCW06031M15FKEA)
RES, 1.15 M, 1%, 0.1 W, 0603; Manufacturer: Vishay-Dale; CompType: Resistor; Value: 1.15Meg; Res_ohm: 1150000; Value_Code: 1M15; Tolerance_%: 1; Power_W: 0.1; Value2: 0.1W; VDC_V: 75; TempCo: 100 ppm/C; SizeArea_mm2: 1.28; SizeX_mm: 1.6; SizeY_mm: 0.8; EIA_Code: E96; U/M: EA; AEC Category: Q200; Green_Lifecycle: Active; Green_REACh: Passed
signal-integrity model Resistor
simulation model Resistor
footprint 0603
footprint 0603M
footprint 0603L
footprint 0603_HV
footprint 0603S
pins: 1, 2

## CRCW06031M18FKEA
designator R?  ValueDisplayed: 1.18M  (hidden comment: CRCW06031M18FKEA)
RES, 1.18 M, 1%, 0.1 W, 0603; Manufacturer: Vishay-Dale; CompType: Resistor; Value: 1.18Meg; Res_ohm: 1180000; Value_Code: 1M18; Tolerance_%: 1; Power_W: 0.1; Value2: 0.1W; VDC_V: 75; TempCo: 100 ppm/C; SizeArea_mm2: 1.28; SizeX_mm: 1.6; SizeY_mm: 0.8; EIA_Code: E96; U/M: EA; AEC Category: Q200
signal-integrity model Resistor
simulation model Resistor
footprint 0603
footprint 0603M
footprint 0603L
footprint 0603_HV
footprint 0603S
pins: 1, 2

## CRCW06031M20FKEA
designator R?  ValueDisplayed: 1.20M  (hidden comment: CRCW06031M20FKEA)
RES, 1.20 M, 1%, 0.1 W, 0603; Manufacturer: Vishay-Dale; CompType: Resistor; Value: 1.20Meg; Res_ohm: 1200000; Value_Code: 1M20; Tolerance_%: 1; Power_W: 0.1; Value2: 0.1W; VDC_V: 75; TempCo: 100 ppm/C; SizeArea_mm2: 1.28; SizeX_mm: 1.6; SizeY_mm: 0.8; U/M: EA; AEC Category: Q200
signal-integrity model Resistor
simulation model Resistor
footprint 0603
footprint 0603M
footprint 0603L
footprint 0603_HV
footprint 0603S
pins: 1, 2

## CRCW06031M20JNEA
designator R?  ValueDisplayed: 1.2M  (hidden comment: CRCW06031M20JNEA)
RES, 1.2 M, 5%, 0.1 W, 0603; Manufacturer: Vishay-Dale; CompType: Resistor; Value: 1.2Meg; Res_ohm: 1200000; Value_Code: 1M20; Tolerance_%: 5; Power_W: 0.1; Value2: 0.1W; VDC_V: 75; TempCo: 200 ppm/C; SizeArea_mm2: 1.28; SizeX_mm: 1.6; SizeY_mm: 0.8; SizeZ_mm: 1; EIA_Code: E24; U/M: EA; AEC Category: Q200; Green_Lifecycle: Active; Green_REACh: Passed
signal-integrity model Resistor
simulation model Resistor
footprint 0603
footprint 0603M
footprint 0603L
footprint 0603_HV
footprint 0603S
pins: 1, 2

## CRCW06031M21FKEA
designator R?  ValueDisplayed: 1.21M  (hidden comment: CRCW06031M21FKEA)
RES, 1.21 M, 1%, 0.1 W, 0603; Manufacturer: Vishay-Dale; CompType: Resistor; Value: 1.21Meg; Res_ohm: 1210000; Value_Code: 1M21; Tolerance_%: 1; Power_W: 0.1; Value2: 0.1W; VDC_V: 75; TempCo: 100 ppm/C; SizeArea_mm2: 1.28; SizeX_mm: 1.6; SizeY_mm: 0.8; EIA_Code: E96; U/M: EA; AEC Category: Q200; Green_Lifecycle: Active; Green_REACh: Passed
signal-integrity model Resistor
simulation model Resistor
footprint 0603
footprint 0603M
footprint 0603L
footprint 0603_HV
footprint 0603S
pins: 1, 2

## CRCW06031M24FKEA
designator R?  ValueDisplayed: 1.24M  (hidden comment: CRCW06031M24FKEA)
RES, 1.24 M, 1%, 0.1 W, 0603; Manufacturer: Vishay-Dale; CompType: Resistor; Value: 1.24Meg; Res_ohm: 1240000; Value_Code: 1M24; Tolerance_%: 1; Power_W: 0.1; Value2: 0.1W; VDC_V: 75; TempCo: 100 ppm/C; SizeArea_mm2: 1.28; SizeX_mm: 1.6; SizeY_mm: 0.8; EIA_Code: E96; U/M: EA; AEC Category: Q200; Green_Lifecycle: Active; Green_REACh: Passed
signal-integrity model Resistor
simulation model Resistor
footprint 0603
footprint 0603M
footprint 0603L
footprint 0603_HV
footprint 0603S
pins: 1, 2

## CRCW06031M27FKEA
designator R?  ValueDisplayed: 1.27M  (hidden comment: CRCW06031M27FKEA)
RES, 1.27 M, 1%, 0.1 W, 0603; Manufacturer: Vishay-Dale; CompType: Resistor; Value: 1.27Meg; Res_ohm: 1270000; Value_Code: 1M27; Tolerance_%: 1; Power_W: 0.1; Value2: 0.1W; VDC_V: 75; TempCo: 100 ppm/C; SizeArea_mm2: 1.28; SizeX_mm: 1.6; SizeY_mm: 0.8; EIA_Code: E96; U/M: EA; AEC Category: Q200
signal-integrity model Resistor
simulation model Resistor
footprint 0603
footprint 0603M
footprint 0603L
footprint 0603_HV
footprint 0603S
pins: 1, 2

## CRCW06031M30FKEA
designator R?  ValueDisplayed: 1.30M  (hidden comment: CRCW06031M30FKEA)
RES, 1.30 M, 1%, 0.1 W, 0603; Manufacturer: Vishay-Dale; CompType: Resistor; Value: 1.30Meg; Res_ohm: 1300000; Value_Code: 1M30; Tolerance_%: 1; Power_W: 0.1; Value2: 0.1W; VDC_V: 75; TempCo: 100 ppm/C; SizeArea_mm2: 1.28; SizeX_mm: 1.6; SizeY_mm: 0.8; EIA_Code: E96; U/M: EA; AEC Category: Q200
signal-integrity model Resistor
simulation model Resistor
footprint 0603
footprint 0603M
footprint 0603L
footprint 0603_HV
footprint 0603S
pins: 1, 2

## CRCW06031M30JNEA
designator R?  ValueDisplayed: 1.3M  (hidden comment: CRCW06031M30JNEA)
RES, 1.3 M, 5%, 0.1 W, 0603; Manufacturer: Vishay-Dale; CompType: Resistor; Value: 1.3Meg; Res_ohm: 1300000; Value_Code: 1M30; Tolerance_%: 5; Power_W: 0.1; Value2: 0.1W; VDC_V: 75; TempCo: 200 ppm/C; SizeArea_mm2: 1.28; SizeX_mm: 1.6; SizeY_mm: 0.8; SizeZ_mm: 1; EIA_Code: E24; U/M: EA; AEC Category: Q200
signal-integrity model Resistor
simulation model Resistor
footprint 0603
footprint 0603M
footprint 0603L
footprint 0603_HV
footprint 0603S
pins: 1, 2

## CRCW06031M33FKEA
designator R?  ValueDisplayed: 1.33M  (hidden comment: CRCW06031M33FKEA)
RES, 1.33 M, 1%, 0.1 W, 0603; Manufacturer: Vishay-Dale; CompType: Resistor; Value: 1.33Meg; Res_ohm: 1330000; Value_Code: 1M33; Tolerance_%: 1; Power_W: 0.1; Value2: 0.1W; VDC_V: 75; TempCo: 100 ppm/C; SizeArea_mm2: 1.28; SizeX_mm: 1.6; SizeY_mm: 0.8; EIA_Code: E96; U/M: EA; AEC Category: Q200
signal-integrity model Resistor
simulation model Resistor
footprint 0603
footprint 0603M
footprint 0603L
footprint 0603_HV
footprint 0603S
pins: 1, 2

## CRCW06031M37FKEA
designator R?  ValueDisplayed: 1.37M  (hidden comment: CRCW06031M37FKEA)
RES, 1.37 M, 1%, 0.1 W, 0603; Manufacturer: Vishay-Dale; CompType: Resistor; Value: 1.37Meg; Res_ohm: 1370000; Value_Code: 1M37; Tolerance_%: 1; Power_W: 0.1; Value2: 0.1W; VDC_V: 75; TempCo: 100 ppm/C; SizeArea_mm2: 1.28; SizeX_mm: 1.6; SizeY_mm: 0.8; EIA_Code: E96; U/M: EA; AEC Category: Q200
signal-integrity model Resistor
simulation model Resistor
footprint 0603
footprint 0603M
footprint 0603L
footprint 0603_HV
footprint 0603S
pins: 1, 2

## CRCW06031M40FKEA
designator R?  ValueDisplayed: 1.40M  (hidden comment: CRCW06031M40FKEA)
RES, 1.40 M, 1%, 0.1 W, 0603; Manufacturer: Vishay-Dale; CompType: Resistor; Value: 1.40Meg; Res_ohm: 1400000; Value_Code: 1M40; Tolerance_%: 1; Power_W: 0.1; Value2: 0.1W; VDC_V: 75; TempCo: 100 ppm/C; SizeArea_mm2: 1.28; SizeX_mm: 1.6; SizeY_mm: 0.8; EIA_Code: E96; U/M: EA; AEC Category: Q200
signal-integrity model Resistor
simulation model Resistor
footprint 0603
footprint 0603M
footprint 0603L
footprint 0603_HV
footprint 0603S
pins: 1, 2

## CRCW06031M43FKEA
designator R?  ValueDisplayed: 1.43M  (hidden comment: CRCW06031M43FKEA)
RES, 1.43 M, 1%, 0.1 W, 0603; Manufacturer: Vishay-Dale; CompType: Resistor; Value: 1.43Meg; Res_ohm: 1430000; Value_Code: 1M43; Tolerance_%: 1; Power_W: 0.1; Value2: 0.1W; VDC_V: 75; TempCo: 100 ppm/C; SizeArea_mm2: 1.28; SizeX_mm: 1.6; SizeY_mm: 0.8; EIA_Code: E96; U/M: EA; AEC Category: Q200; Green_Lifecycle: Active; Green_REACh: Passed
signal-integrity model Resistor
simulation model Resistor
footprint 0603
footprint 0603M
footprint 0603L
footprint 0603_HV
footprint 0603S
pins: 1, 2

## CRCW06031M47FKEA
designator R?  ValueDisplayed: 1.47M  (hidden comment: CRCW06031M47FKEA)
RES, 1.47 M, 1%, 0.1 W, 0603; Manufacturer: Vishay-Dale; CompType: Resistor; Value: 1.47Meg; Res_ohm: 1470000; Value_Code: 1M47; Tolerance_%: 1; Power_W: 0.1; Value2: 0.1W; VDC_V: 75; TempCo: 100 ppm/C; SizeArea_mm2: 1.28; SizeX_mm: 1.6; SizeY_mm: 0.8; EIA_Code: E96; U/M: EA; AEC Category: Q200
signal-integrity model Resistor
simulation model Resistor
footprint 0603
footprint 0603M
footprint 0603L
footprint 0603_HV
footprint 0603S
pins: 1, 2

## CRCW06031M50FKEA
designator R?  ValueDisplayed: 1.50M  (hidden comment: CRCW06031M50FKEA)
RES, 1.50 M, 1%, 0.1 W, 0603; Manufacturer: Vishay-Dale; CompType: Resistor; Value: 1.50Meg; Res_ohm: 1500000; Value_Code: 1M50; Tolerance_%: 1; Power_W: 0.1; Value2: 0.1W; VDC_V: 75; TempCo: 100 ppm/C; SizeArea_mm2: 1.28; SizeX_mm: 1.6; SizeY_mm: 0.8; EIA_Code: E96; U/M: EA; AEC Category: Q200
signal-integrity model Resistor
simulation model Resistor
footprint 0603
footprint 0603M
footprint 0603L
footprint 0603_HV
footprint 0603S
pins: 1, 2

## CRCW06031M50JNEA
designator R?  ValueDisplayed: 1.5M  (hidden comment: CRCW06031M50JNEA)
RES, 1.5 M, 5%, 0.1 W, 0603; Manufacturer: Vishay-Dale; CompType: Resistor; Value: 1.5Meg; Res_ohm: 1500000; Value_Code: 1M50; Tolerance_%: 5; Power_W: 0.1; Value2: 0.1W; VDC_V: 75; TempCo: 200 ppm/C; SizeArea_mm2: 1.28; SizeX_mm: 1.6; SizeY_mm: 0.8; SizeZ_mm: 1; EIA_Code: E24; U/M: EA; AEC Category: Q200
signal-integrity model Resistor
simulation model Resistor
footprint 0603
footprint 0603M
footprint 0603L
footprint 0603_HV
footprint 0603S
pins: 1, 2

## CRCW06031M54FKEA
designator R?  ValueDisplayed: 1.54M  (hidden comment: CRCW06031M54FKEA)
RES, 1.54 M, 1%, 0.1 W, 0603; Manufacturer: Vishay-Dale; CompType: Resistor; Value: 1.54Meg; Res_ohm: 1540000; Value_Code: 1M54; Tolerance_%: 1; Power_W: 0.1; Value2: 0.1W; VDC_V: 75; TempCo: 100 ppm/C; SizeArea_mm2: 1.28; SizeX_mm: 1.6; SizeY_mm: 0.8; EIA_Code: E96; U/M: EA; AEC Category: Q200
signal-integrity model Resistor
simulation model Resistor
footprint 0603
footprint 0603M
footprint 0603L
footprint 0603_HV
footprint 0603S
pins: 1, 2

## CRCW06031M58FKEA
designator R?  ValueDisplayed: 1.58M  (hidden comment: CRCW06031M58FKEA)
RES, 1.58 M, 1%, 0.1 W, 0603; Manufacturer: Vishay-Dale; CompType: Resistor; Value: 1.58Meg; Res_ohm: 1580000; Value_Code: 1M58; Tolerance_%: 1; Power_W: 0.1; Value2: 0.1W; VDC_V: 75; TempCo: 100 ppm/C; SizeArea_mm2: 1.28; SizeX_mm: 1.6; SizeY_mm: 0.8; EIA_Code: E96; U/M: EA; AEC Category: Q200
signal-integrity model Resistor
simulation model Resistor
footprint 0603
footprint 0603M
footprint 0603L
footprint 0603_HV
footprint 0603S
pins: 1, 2

## CRCW06031M60FKEA
designator R?  ValueDisplayed: 1.60M  (hidden comment: CRCW06031M60FKEA)
RES, 1.60 M, 1%, 0.1 W, AEC-Q200 Grade 0, 0603; Manufacturer: Vishay-Dale; CompType: Resistor; Value: 1.60Meg; Res_ohm: 1600000; Value_Code: 1M60; Tolerance_%: 1; Power_W: 0.1; Value2: 0.1W; VDC_V: 75; TempCo: 100 ppm/C; SizeArea_mm2: 1.28; SizeX_mm: 1.6; SizeY_mm: 0.8; U/M: EA; AEC Category: Q200; AEC Qualified: Y; AEC Grade: 0
signal-integrity model Resistor
simulation model Resistor
footprint 0603
footprint 0603M
footprint 0603L
footprint 0603_HV
footprint 0603S
pins: 1, 2

## CRCW06031M60JNEA
designator R?  ValueDisplayed: 1.6M  (hidden comment: CRCW06031M60JNEA)
RES, 1.6 M, 5%, 0.1 W, 0603; Manufacturer: Vishay-Dale; CompType: Resistor; Value: 1.6Meg; Res_ohm: 1600000; Value_Code: 1M60; Tolerance_%: 5; Power_W: 0.1; Value2: 0.1W; VDC_V: 75; TempCo: 200 ppm/C; SizeArea_mm2: 1.28; SizeX_mm: 1.6; SizeY_mm: 0.8; SizeZ_mm: 1; EIA_Code: E24; U/M: EA; AEC Category: Q200; Green_Lifecycle: Active; Green_REACh: Passed
signal-integrity model Resistor
simulation model Resistor
footprint 0603
footprint 0603M
footprint 0603L
footprint 0603_HV
footprint 0603S
pins: 1, 2

## CRCW06031M62FKEA
designator R?  ValueDisplayed: 1.62M  (hidden comment: CRCW06031M62FKEA)
RES, 1.62 M, 1%, 0.1 W, 0603; Manufacturer: Vishay-Dale; CompType: Resistor; Value: 1.62Meg; Res_ohm: 1620000; Value_Code: 1M62; Tolerance_%: 1; Power_W: 0.1; Value2: 0.1W; VDC_V: 75; TempCo: 100 ppm/C; SizeArea_mm2: 1.28; SizeX_mm: 1.6; SizeY_mm: 0.8; EIA_Code: E96; U/M: EA; AEC Category: Q200
signal-integrity model Resistor
simulation model Resistor
footprint 0603
footprint 0603M
footprint 0603L
footprint 0603_HV
footprint 0603S
pins: 1, 2

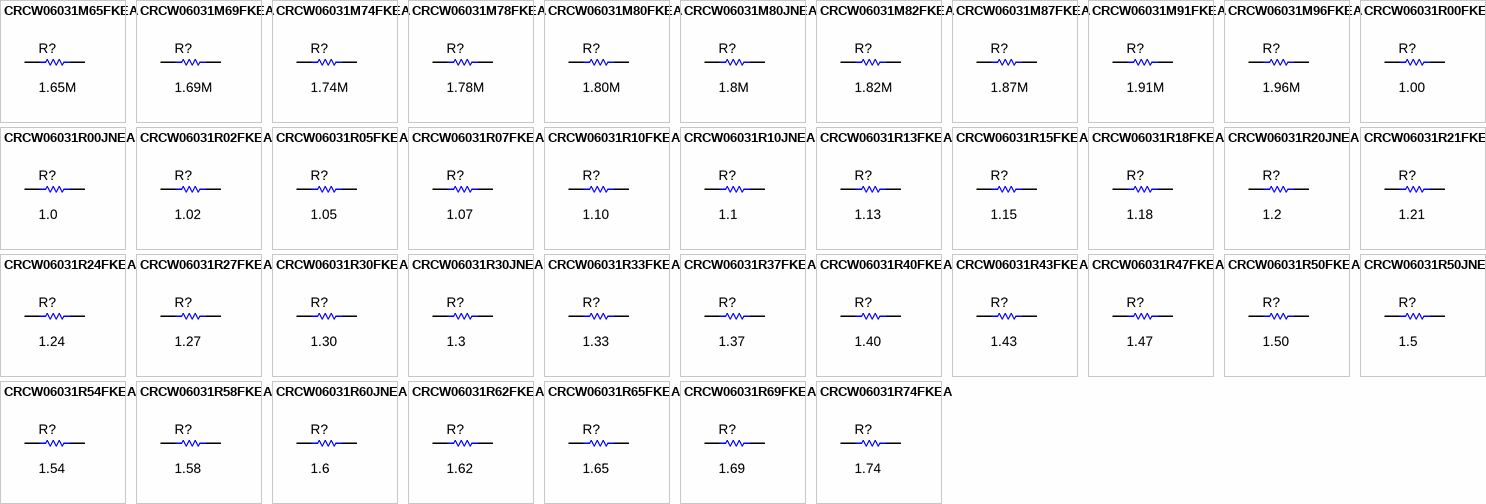
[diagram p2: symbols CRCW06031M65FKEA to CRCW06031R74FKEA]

## CRCW06031M65FKEA
designator R?  ValueDisplayed: 1.65M  (hidden comment: CRCW06031M65FKEA)
RES, 1.65 M, 1%, 0.1 W, 0603; Manufacturer: Vishay-Dale; CompType: Resistor; Value: 1.65Meg; Res_ohm: 1650000; Value_Code: 1M65; Tolerance_%: 1; Power_W: 0.1; Value2: 0.1W; VDC_V: 75; TempCo: 100 ppm/C; SizeArea_mm2: 1.28; SizeX_mm: 1.6; SizeY_mm: 0.8; EIA_Code: E96; U/M: EA; AEC Category: Q200; Green_Lifecycle: Active; Green_REACh: Passed
signal-integrity model Resistor
simulation model Resistor
footprint 0603
footprint 0603M
footprint 0603L
footprint 0603_HV
footprint 0603S
pins: 1, 2

## CRCW06031M69FKEA
designator R?  ValueDisplayed: 1.69M  (hidden comment: CRCW06031M69FKEA)
RES, 1.69 M, 1%, 0.1 W, 0603; Manufacturer: Vishay-Dale; CompType: Resistor; Value: 1.69Meg; Res_ohm: 1690000; Value_Code: 1M69; Tolerance_%: 1; Power_W: 0.1; Value2: 0.1W; VDC_V: 75; TempCo: 100 ppm/C; SizeArea_mm2: 1.28; SizeX_mm: 1.6; SizeY_mm: 0.8; EIA_Code: E96; U/M: EA; AEC Category: Q200
signal-integrity model Resistor
simulation model Resistor
footprint 0603
footprint 0603M
footprint 0603L
footprint 0603_HV
footprint 0603S
pins: 1, 2

## CRCW06031M74FKEA
designator R?  ValueDisplayed: 1.74M  (hidden comment: CRCW06031M74FKEA)
RES, 1.74 M, 1%, 0.1 W, 0603; Manufacturer: Vishay-Dale; CompType: Resistor; Value: 1.74Meg; Res_ohm: 1740000; Value_Code: 1M74; Tolerance_%: 1; Power_W: 0.1; Value2: 0.1W; VDC_V: 75; TempCo: 100 ppm/C; SizeArea_mm2: 1.28; SizeX_mm: 1.6; SizeY_mm: 0.8; EIA_Code: E96; U/M: EA; AEC Category: Q200
signal-integrity model Resistor
simulation model Resistor
footprint 0603
footprint 0603M
footprint 0603L
footprint 0603_HV
footprint 0603S
pins: 1, 2

## CRCW06031M78FKEA
designator R?  ValueDisplayed: 1.78M  (hidden comment: CRCW06031M78FKEA)
RES, 1.78 M, 1%, 0.1 W, 0603; Manufacturer: Vishay-Dale; CompType: Resistor; Value: 1.78Meg; Res_ohm: 1780000; Value_Code: 1M78; Tolerance_%: 1; Power_W: 0.1; Value2: 0.1W; VDC_V: 75; TempCo: 100 ppm/C; SizeArea_mm2: 1.28; SizeX_mm: 1.6; SizeY_mm: 0.8; EIA_Code: E96; U/M: EA; AEC Category: Q200
signal-integrity model Resistor
simulation model Resistor
footprint 0603
footprint 0603M
footprint 0603L
footprint 0603_HV
footprint 0603S
pins: 1, 2

## CRCW06031M80FKEA
designator R?  ValueDisplayed: 1.80M  (hidden comment: CRCW06031M80FKEA)
RES, 1.80 M, 1%, 0.1 W, AEC-Q200 Grade 0, 0603; Manufacturer: Vishay-Dale; CompType: Resistor; Value: 1.80Meg; Res_ohm: 1800000; Value_Code: 1M80; Tolerance_%: 1; Power_W: 0.1; Value2: 0.1W; VDC_V: 75; TempCo: 100 ppm/C; SizeArea_mm2: 1.28; SizeX_mm: 1.6; SizeY_mm: 0.8; U/M: EA; AEC Category: Q200; AEC Qualified: Y; AEC Grade: 0; Green_Lifecycle: Active; Green_REACh: Passed
signal-integrity model Resistor
simulation model Resistor
footprint 0603
footprint 0603M
footprint 0603L
footprint 0603_HV
footprint 0603S
pins: 1, 2

## CRCW06031M80JNEA
designator R?  ValueDisplayed: 1.8M  (hidden comment: CRCW06031M80JNEA)
RES, 1.8 M, 5%, 0.1 W, 0603; Manufacturer: Vishay-Dale; CompType: Resistor; Value: 1.8Meg; Res_ohm: 1800000; Value_Code: 1M80; Tolerance_%: 5; Power_W: 0.1; Value2: 0.1W; VDC_V: 75; TempCo: 200 ppm/C; SizeArea_mm2: 1.28; SizeX_mm: 1.6; SizeY_mm: 0.8; SizeZ_mm: 1; EIA_Code: E24; U/M: EA; AEC Category: Q200; Green_Lifecycle: Active; Green_REACh: Passed
signal-integrity model Resistor
simulation model Resistor
footprint 0603
footprint 0603M
footprint 0603L
footprint 0603_HV
footprint 0603S
pins: 1, 2

## CRCW06031M82FKEA
designator R?  ValueDisplayed: 1.82M  (hidden comment: CRCW06031M82FKEA)
RES, 1.82 M, 1%, 0.1 W, 0603; Manufacturer: Vishay-Dale; CompType: Resistor; Value: 1.82Meg; Res_ohm: 1820000; Value_Code: 1M82; Tolerance_%: 1; Power_W: 0.1; Value2: 0.1W; VDC_V: 75; TempCo: 100 ppm/C; SizeArea_mm2: 1.28; SizeX_mm: 1.6; SizeY_mm: 0.8; EIA_Code: E96; U/M: EA; AEC Category: Q200; Green_Lifecycle: Active; Green_REACh: Passed
signal-integrity model Resistor
simulation model Resistor
footprint 0603
footprint 0603M
footprint 0603L
footprint 0603_HV
footprint 0603S
pins: 1, 2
